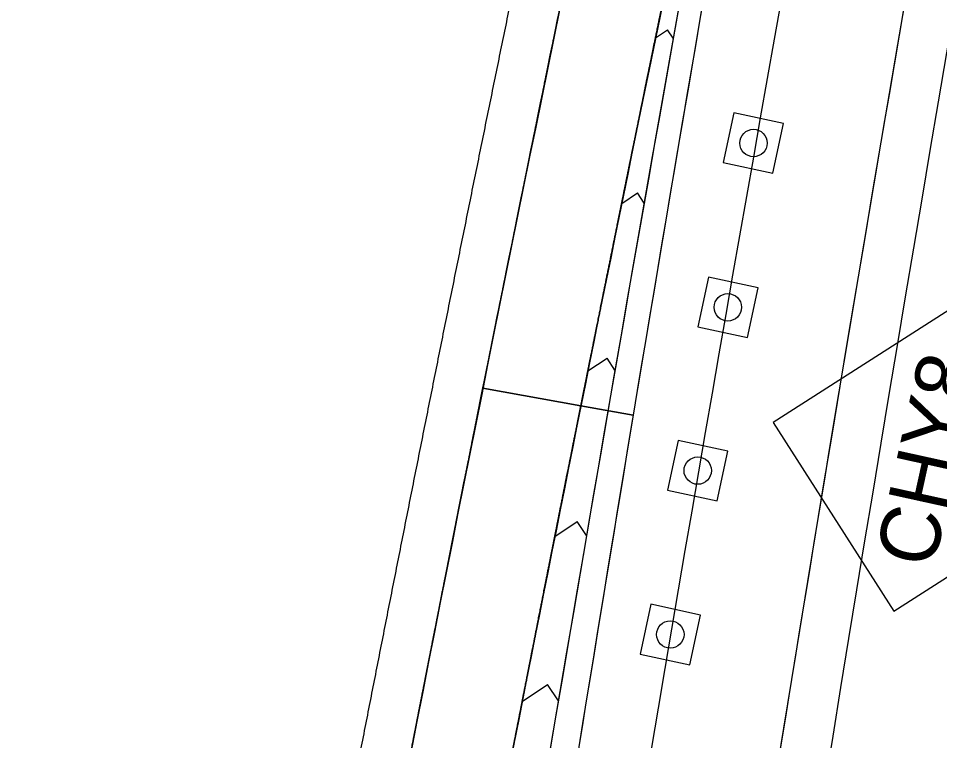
# Model space of a CAD drawing. Extents: x 14104283 to 14121738, y 8635219 to 8671666.
# Drawn here: x 14107950.2 to 14108061.2, y 8640438 to 8640525 of the extents above; entities that cross this region are included whole.
import ezdxf

# ---------------------------------------------------------------- set-up
doc = ezdxf.new("R2010")
doc.units = 0
for name, color, linetype in [('Cell', 7, 'Continuous'), ('Default', 7, 'Continuous'), ('dsnPaintExistingBrokenLaneLineWhite', 7, 'Continuous'), ('dsnPaintExistingChannelizingLaneWhite', 7, 'Continuous'), ('dsnPaintExistingEdgeLineRightWhite', 7, 'Continuous'), ('dsnStdLabel', 7, 'Continuous'), ('dsnStgShadingPrevPav', 7, 'Continuous')]:
    doc.layers.add(name, color=color, linetype=linetype)

msp = doc.modelspace()

# ---------------------------------------------------------------- linework, layer by layer
at = {"layer": 'Cell'}
for points in [[(14108041.1, 8640506.32), (14108042.39, 8640512.31), (14108036.4, 8640513.6), (14108035.11, 8640507.61), (14108041.1, 8640506.32)], [(14108041.1, 8640506.32), (14108042.39, 8640512.31), (14108036.4, 8640513.6), (14108035.11, 8640507.61), (14108041.1, 8640506.32)], [(14108038.02, 8640486.52), (14108039.31, 8640492.51), (14108033.32, 8640493.8), (14108032.03, 8640487.81), (14108038.02, 8640486.52)], [(14108038.02, 8640486.52), (14108039.31, 8640492.51), (14108033.32, 8640493.8), (14108032.03, 8640487.81), (14108038.02, 8640486.52)], [(14108034.38, 8640466.84), (14108035.67, 8640472.83), (14108029.68, 8640474.12), (14108028.39, 8640468.13), (14108034.38, 8640466.84)], [(14108034.38, 8640466.84), (14108035.67, 8640472.83), (14108029.68, 8640474.12), (14108028.39, 8640468.13), (14108034.38, 8640466.84)], [(14108031.08, 8640447.09), (14108032.37, 8640453.08), (14108026.38, 8640454.37), (14108025.09, 8640448.38), (14108031.08, 8640447.09)], [(14108031.08, 8640447.09), (14108032.37, 8640453.08), (14108026.38, 8640454.37), (14108025.09, 8640448.38), (14108031.08, 8640447.09)]]:
    msp.add_lwpolyline(points, dxfattribs=at)
for centre in [(14108038.75, 8640509.96), (14108038.75, 8640509.96), (14108035.67, 8640490.16), (14108035.67, 8640490.16), (14108032.03, 8640470.48), (14108032.03, 8640470.48), (14108028.73, 8640450.73), (14108028.73, 8640450.73)]:
    msp.add_circle(centre, 1.65, dxfattribs=at)
at = {"layer": 'Default'}
for centre, radius, start, end in [((14117394.14, 8638857.08), 9512, 167.610212, 171.325989), ((14117394.14, 8638857.08), 9500, 167.610212, 171.325989), ((14117342.69, 8638609.63), 9522.13, 167.509575, 168.915877), ((14117342.69, 8638609.63), 9510.13, 167.921867, 168.915877), ((14117350.61, 8638608.07), 9530.2, 168.915826, 170.320937)]:
    msp.add_arc(centre, radius, start, end, dxfattribs=at)
at = {"layer": 'dsnPaintExistingBrokenLaneLineWhite'}
msp.add_arc((14117394.14, 8638857.08), 9500, 167.610212, 171.325989, dxfattribs=at)
at = {"layer": 'dsnPaintExistingChannelizingLaneWhite'}
for p, q in [((14108026.95, 8640522.65), (14108028.41, 8640523.61)), ((14108029.08, 8640522.59), (14108028.41, 8640523.61)), ((14108022.87, 8640502.69), (14108024.77, 8640503.94)), ((14108025.58, 8640502.72), (14108024.77, 8640503.94)), ((14108018.8, 8640482.51), (14108021.1, 8640484.04)), ((14108022.06, 8640482.58), (14108021.1, 8640484.04)), ((14108014.81, 8640462.56), (14108017.51, 8640464.36)), ((14108018.63, 8640462.68), (14108017.51, 8640464.36)), ((14108010.88, 8640442.64), (14108013.92, 8640444.69)), ((14108015.24, 8640442.73), (14108013.92, 8640444.69))]:
    msp.add_line(p, q, dxfattribs=at)
for centre, radius, start, end in [((14117394.14, 8638857.08), 9512, 169.444425, 171.325989), ((14117342.69, 8638609.63), 9510.13, 167.921867, 168.915877)]:
    msp.add_arc(centre, radius, start, end, dxfattribs=at)
at = {"layer": 'dsnPaintExistingEdgeLineRightWhite'}
for centre, radius, start, end in [((14117342.69, 8638609.63), 9522.13, 167.509575, 168.915877), ((14117350.61, 8638608.07), 9530.2, 168.915826, 170.320937)]:
    msp.add_arc(centre, radius, start, end, dxfattribs=at)
at = {"layer": 'dsnStdLabel'}
msp.add_lwpolyline([(14108055.67, 8640453.53), (14108078.42, 8640468.08), (14108063.87, 8640490.82), (14108041.12, 8640476.27)], close=True, dxfattribs=at)
at = {"layer": 'dsnStgShadingPrevPav'}
for p, q in [((14108006.14, 8640480.41), (14108017.94, 8640478.29)), ((14108017.94, 8640478.29), (14108006.14, 8640480.41)), ((14108017.94, 8640478.29), (14108024.25, 8640477.15)), ((14108024.25, 8640477.15), (14108017.94, 8640478.29))]:
    msp.add_line(p, q, dxfattribs=at)
for radius, start, end in [(9488, 167.610212, 172.222077), (9482, 167.610212, 172.222077), (9512, 169.413861, 172.222077), (9512, 169.413861, 170.574102), (9488, 169.413861, 172.222077), (9512, 170.574102, 171.702544)]:
    msp.add_arc((14117407.82, 8638919.35), radius, start, end, dxfattribs=at)
for points, degree in [([(14108040.07, 8640670.33), (14108039.11, 8640666.01), (14108035.79, 8640651.03), (14108029.85, 8640623.7), (14108025.19, 8640602.04), (14108020.26, 8640578.84), (14108015.47, 8640556.04), (14108010.72, 8640533.12), (14108006.03, 8640510.22), (14108001.39, 8640487.29), (14107996.81, 8640464.36), (14107992.28, 8640441.41), (14107987.82, 8640418.46), (14107983.4, 8640395.49), (14107979.05, 8640372.51), (14107974.75, 8640349.53), (14107970.51, 8640326.51), (14107966.33, 8640303.59), (14107962.15, 8640280.24), (14107958.29, 8640258.43), (14107953.48, 8640230.88), (14107950.9, 8640215.75), (14107950.15, 8640211.39)], 2), ([(14107956.07, 8640210.37), (14107957.38, 8640218.06), (14107960.02, 8640233.43), (14107964.04, 8640256.47), (14107968.11, 8640279.5), (14107972.24, 8640302.51), (14107976.42, 8640325.52), (14107980.66, 8640348.51), (14107984.96, 8640371.49), (14107989.32, 8640394.46), (14107993.73, 8640417.41), (14107998.19, 8640440.35), (14108002.71, 8640463.28), (14108007.29, 8640486.2), (14108011.92, 8640509.1), (14108016.61, 8640531.99), (14108021.36, 8640554.87), (14108026.16, 8640577.73), (14108031.01, 8640600.58), (14108035.93, 8640623.41), (14108040.89, 8640646.24), (14108044.25, 8640661.44), (14108045.92, 8640669.04)], 3), ([(14108014.97, 8640523.98), (14108015.44, 8640526.27), (14108015.91, 8640528.56), (14108016.39, 8640530.85)], 2), ([(14108028.21, 8640528.82), (14108027.82, 8640526.91), (14108027.43, 8640525.01), (14108027.04, 8640523.1)], 2), ([(14108027.04, 8640523.1), (14108027.43, 8640525.01), (14108027.82, 8640526.91), (14108028.21, 8640528.82)], 2), ([(14108014.74, 8640522.84), (14108014.82, 8640523.22), (14108014.9, 8640523.6), (14108014.97, 8640523.98)], 2), ([(14108013.33, 8640515.97), (14108013.8, 8640518.26), (14108014.27, 8640520.55), (14108014.74, 8640522.84)], 2), ([(14108027.04, 8640523.1), (14108026.72, 8640521.58), (14108026.41, 8640520.05), (14108026.1, 8640518.53)], 2), ([(14108026.1, 8640518.53), (14108026.41, 8640520.05), (14108026.72, 8640521.58), (14108027.04, 8640523.1)], 2), ([(14108026.1, 8640518.53), (14108026.02, 8640518.15), (14108025.94, 8640517.77), (14108025.86, 8640517.39)], 2), ([(14108025.86, 8640517.39), (14108025.94, 8640517.77), (14108026.02, 8640518.15), (14108026.1, 8640518.53)], 2), ([(14108025.86, 8640517.39), (14108025.71, 8640516.63), (14108025.55, 8640515.86), (14108025.4, 8640515.1)], 2), ([(14108025.4, 8640515.1), (14108025.55, 8640515.86), (14108025.71, 8640516.63), (14108025.86, 8640517.39)], 2), ([(14108012.4, 8640511.39), (14108012.71, 8640512.92), (14108013.02, 8640514.44), (14108013.33, 8640515.97)], 2), ([(14108025.4, 8640515.1), (14108025.24, 8640514.34), (14108025.09, 8640513.58), (14108024.93, 8640512.81)], 2), ([(14108024.93, 8640512.81), (14108025.09, 8640513.58), (14108025.24, 8640514.34), (14108025.4, 8640515.1)], 2), ([(14108024.93, 8640512.81), (14108024.7, 8640511.67), (14108024.46, 8640510.53), (14108024.23, 8640509.38)], 2), ([(14108024.23, 8640509.38), (14108024.46, 8640510.53), (14108024.7, 8640511.67), (14108024.93, 8640512.81)], 2), ([(14108012.17, 8640510.25), (14108012.24, 8640510.63), (14108012.32, 8640511.01), (14108012.4, 8640511.39)], 2), ([(14108011.93, 8640509.1), (14108012.01, 8640509.48), (14108012.09, 8640509.86), (14108012.17, 8640510.25)], 2), ([(14108024.23, 8640509.38), (14108024.15, 8640509), (14108024.07, 8640508.62), (14108024, 8640508.24)], 2), ([(14108024, 8640508.24), (14108024.07, 8640508.62), (14108024.15, 8640509), (14108024.23, 8640509.38)], 2), ([(14108011.47, 8640506.81), (14108011.62, 8640507.57), (14108011.78, 8640508.34), (14108011.93, 8640509.1)], 2), ([(14108024, 8640508.24), (14108023.92, 8640507.86), (14108023.84, 8640507.48), (14108023.76, 8640507.1)], 2), ([(14108023.76, 8640507.1), (14108023.84, 8640507.48), (14108023.92, 8640507.86), (14108024, 8640508.24)], 2), ([(14108023.76, 8640507.1), (14108023.69, 8640506.72), (14108023.61, 8640506.34), (14108023.53, 8640505.95)], 2), ([(14108023.53, 8640505.95), (14108023.61, 8640506.34), (14108023.69, 8640506.72), (14108023.76, 8640507.1)], 2), ([(14108010.77, 8640503.38), (14108011, 8640504.52), (14108011.23, 8640505.67), (14108011.47, 8640506.81)], 2), ([(14108023.53, 8640505.95), (14108023.45, 8640505.57), (14108023.38, 8640505.19), (14108023.3, 8640504.81)], 2), ([(14108023.3, 8640504.81), (14108023.38, 8640505.19), (14108023.45, 8640505.57), (14108023.53, 8640505.95)], 2), ([(14108023.3, 8640504.81), (14108023.22, 8640504.43), (14108023.14, 8640504.05), (14108023.07, 8640503.67)], 2), ([(14108023.07, 8640503.67), (14108023.14, 8640504.05), (14108023.22, 8640504.43), (14108023.3, 8640504.81)], 2), ([(14108023.07, 8640503.67), (14108022.99, 8640503.29), (14108022.91, 8640502.91), (14108022.83, 8640502.52)], 2), ([(14108022.83, 8640502.52), (14108022.91, 8640502.91), (14108022.99, 8640503.29), (14108023.07, 8640503.67)], 2), ([(14108010.3, 8640501.09), (14108010.46, 8640501.85), (14108010.61, 8640502.61), (14108010.77, 8640503.38)], 2), ([(14108022.83, 8640502.52), (14108022.76, 8640502.14), (14108022.68, 8640501.76), (14108022.6, 8640501.38)], 2), ([(14108022.6, 8640501.38), (14108022.68, 8640501.76), (14108022.76, 8640502.14), (14108022.83, 8640502.52)], 2), ([(14108022.6, 8640501.38), (14108022.52, 8640501), (14108022.45, 8640500.62), (14108022.37, 8640500.24)], 2), ([(14108022.37, 8640500.24), (14108022.45, 8640500.62), (14108022.52, 8640501), (14108022.6, 8640501.38)], 2), ([(14108009.38, 8640496.5), (14108009.69, 8640498.03), (14108009.99, 8640499.56), (14108010.3, 8640501.09)], 2), ([(14108022.37, 8640500.24), (14108021.98, 8640498.33), (14108021.6, 8640496.43), (14108021.21, 8640494.52)], 2), ([(14108021.21, 8640494.52), (14108021.6, 8640496.43), (14108021.98, 8640498.33), (14108022.37, 8640500.24)], 2), ([(14108009.15, 8640495.36), (14108009.22, 8640495.74), (14108009.3, 8640496.12), (14108009.38, 8640496.5)], 2), ([(14108008.45, 8640491.92), (14108008.68, 8640493.07), (14108008.91, 8640494.21), (14108009.15, 8640495.36)], 2), ([(14108021.21, 8640494.52), (14108020.52, 8640491.09), (14108019.83, 8640487.66), (14108019.14, 8640484.22)], 2), ([(14108019.14, 8640484.22), (14108019.83, 8640487.66), (14108020.52, 8640491.09), (14108021.21, 8640494.52)], 2), ([(14108007.99, 8640489.63), (14108008.14, 8640490.4), (14108008.3, 8640491.16), (14108008.45, 8640491.92)], 2), ([(14108007.76, 8640488.49), (14108007.84, 8640488.87), (14108007.91, 8640489.25), (14108007.99, 8640489.63)], 2), ([(14108007.53, 8640487.34), (14108007.61, 8640487.72), (14108007.68, 8640488.11), (14108007.76, 8640488.49)], 2), ([(14108007.3, 8640486.2), (14108007.38, 8640486.58), (14108007.45, 8640486.96), (14108007.53, 8640487.34)], 2), ([(14108006.84, 8640483.91), (14108006.99, 8640484.67), (14108007.15, 8640485.43), (14108007.3, 8640486.2)], 2), ([(14108006.38, 8640481.61), (14108006.53, 8640482.38), (14108006.69, 8640483.14), (14108006.84, 8640483.91)], 2), ([(14108019.14, 8640484.22), (14108019.06, 8640483.84), (14108018.98, 8640483.46), (14108018.91, 8640483.08)], 2), ([(14108018.91, 8640483.08), (14108018.98, 8640483.46), (14108019.06, 8640483.84), (14108019.14, 8640484.22)], 2), ([(14108018.91, 8640483.08), (14108018.75, 8640482.32), (14108018.6, 8640481.55), (14108018.45, 8640480.79)], 2), ([(14108018.45, 8640480.79), (14108018.6, 8640481.55), (14108018.75, 8640482.32), (14108018.91, 8640483.08)], 2), ([(14108006.14, 8640480.41), (14108006.22, 8640480.81), (14108006.3, 8640481.21), (14108006.38, 8640481.61)], 2), ([(14108005.46, 8640477.03), (14108005.69, 8640478.16), (14108005.91, 8640479.28), (14108006.14, 8640480.41)], 2), ([(14108018.45, 8640480.79), (14108018.29, 8640480.03), (14108018.14, 8640479.27), (14108017.99, 8640478.5)], 2), ([(14108017.99, 8640478.5), (14108018.14, 8640479.27), (14108018.29, 8640480.03), (14108018.45, 8640480.79)], 2), ([(14108017.94, 8640478.29), (14108017.88, 8640477.98), (14108017.82, 8640477.67), (14108017.76, 8640477.36)], 2), ([(14108017.76, 8640477.36), (14108017.82, 8640477.67), (14108017.88, 8640477.98), (14108017.94, 8640478.29)], 2), ([(14108017.99, 8640478.5), (14108017.97, 8640478.43), (14108017.96, 8640478.36), (14108017.94, 8640478.29)], 2), ([(14108017.94, 8640478.29), (14108017.96, 8640478.36), (14108017.97, 8640478.43), (14108017.99, 8640478.5)], 2), ([(14108005.23, 8640475.89), (14108005.31, 8640476.27), (14108005.38, 8640476.65), (14108005.46, 8640477.03)], 2), ([(14108017.76, 8640477.36), (14108017.68, 8640476.98), (14108017.61, 8640476.6), (14108017.53, 8640476.22)], 2), ([(14108017.53, 8640476.22), (14108017.61, 8640476.6), (14108017.68, 8640476.98), (14108017.76, 8640477.36)], 2), ([(14108005, 8640474.74), (14108005.08, 8640475.12), (14108005.16, 8640475.5), (14108005.23, 8640475.89)], 2), ([(14108017.53, 8640476.22), (14108016.84, 8640472.78), (14108016.16, 8640469.35), (14108015.47, 8640465.92)], 2), ([(14108015.47, 8640465.92), (14108016.16, 8640469.35), (14108016.84, 8640472.78), (14108017.53, 8640476.22)], 2), ([(14108003.63, 8640467.87), (14108004.09, 8640470.16), (14108004.55, 8640472.45), (14108005, 8640474.74)], 2), ([(14108003.4, 8640466.72), (14108003.48, 8640467.1), (14108003.56, 8640467.48), (14108003.63, 8640467.87)], 2), ([(14108002.72, 8640463.28), (14108002.95, 8640464.43), (14108003.18, 8640465.57), (14108003.4, 8640466.72)], 2), ([(14108015.47, 8640465.92), (14108015.4, 8640465.53), (14108015.32, 8640465.15), (14108015.25, 8640464.77)], 2), ([(14108015.25, 8640464.77), (14108015.32, 8640465.15), (14108015.4, 8640465.53), (14108015.47, 8640465.92)], 2), ([(14108015.25, 8640464.77), (14108015.17, 8640464.39), (14108015.09, 8640464.01), (14108015.02, 8640463.63)], 2), ([(14108015.02, 8640463.63), (14108015.09, 8640464.01), (14108015.17, 8640464.39), (14108015.25, 8640464.77)], 2), ([(14108015.02, 8640463.63), (14108014.87, 8640462.86), (14108014.71, 8640462.1), (14108014.56, 8640461.34)], 2), ([(14108014.56, 8640461.34), (14108014.71, 8640462.1), (14108014.87, 8640462.86), (14108015.02, 8640463.63)], 2), ([(14108002.49, 8640462.13), (14108002.57, 8640462.52), (14108002.65, 8640462.9), (14108002.72, 8640463.28)], 2), ([(14108002.27, 8640460.99), (14108002.34, 8640461.37), (14108002.42, 8640461.75), (14108002.49, 8640462.13)], 2), ([(14108002.04, 8640459.84), (14108002.12, 8640460.22), (14108002.19, 8640460.61), (14108002.27, 8640460.99)], 2), ([(14108014.56, 8640461.34), (14108014.41, 8640460.57), (14108014.26, 8640459.81), (14108014.11, 8640459.05)], 2), ([(14108014.11, 8640459.05), (14108014.26, 8640459.81), (14108014.41, 8640460.57), (14108014.56, 8640461.34)], 2), ([(14108001.13, 8640455.26), (14108001.43, 8640456.79), (14108001.74, 8640458.31), (14108002.04, 8640459.84)], 2), ([(14108014.11, 8640459.05), (14108013.5, 8640455.99), (14108012.9, 8640452.94), (14108012.3, 8640449.89)], 2), ([(14108012.3, 8640449.89), (14108012.9, 8640452.94), (14108013.5, 8640455.99), (14108014.11, 8640459.05)], 2), ([(14108000.91, 8640454.11), (14108000.98, 8640454.49), (14108001.06, 8640454.87), (14108001.13, 8640455.26)], 2), ([(14107999.78, 8640448.38), (14108000.15, 8640450.29), (14108000.53, 8640452.2), (14108000.91, 8640454.11)], 2), ([(14108012.3, 8640449.89), (14108011.92, 8640447.98), (14108011.55, 8640446.07), (14108011.17, 8640444.16)], 2), ([(14108011.17, 8640444.16), (14108011.55, 8640446.07), (14108011.92, 8640447.98), (14108012.3, 8640449.89)], 2), ([(14107999.55, 8640447.23), (14107999.63, 8640447.61), (14107999.7, 8640448), (14107999.78, 8640448.38)], 2), ([(14107998.87, 8640443.79), (14107999.1, 8640444.94), (14107999.33, 8640446.09), (14107999.55, 8640447.23)], 2), ([(14107998.2, 8640440.35), (14107998.42, 8640441.5), (14107998.65, 8640442.65), (14107998.87, 8640443.79)], 2), ([(14108011.17, 8640444.16), (14108010.87, 8640442.64), (14108010.57, 8640441.11), (14108010.27, 8640439.58)], 2), ([(14108010.27, 8640439.58), (14108010.57, 8640441.11), (14108010.87, 8640442.64), (14108011.17, 8640444.16)], 2), ([(14107997.98, 8640439.2), (14107998.05, 8640439.59), (14107998.13, 8640439.97), (14107998.2, 8640440.35)], 2), ([(14107997.75, 8640438.06), (14107997.83, 8640438.44), (14107997.9, 8640438.82), (14107997.98, 8640439.2)], 2), ([(14108010.27, 8640439.58), (14108010.2, 8640439.2), (14108010.12, 8640438.82), (14108010.05, 8640438.44)], 2), ([(14108010.05, 8640438.44), (14108010.12, 8640438.82), (14108010.2, 8640439.2), (14108010.27, 8640439.58)], 2), ([(14108010.05, 8640438.44), (14108009.9, 8640437.67), (14108009.75, 8640436.91), (14108009.6, 8640436.15)], 2), ([(14108009.6, 8640436.15), (14108009.75, 8640436.91), (14108009.9, 8640437.67), (14108010.05, 8640438.44)], 2), ([(14107995.51, 8640426.59), (14107996.26, 8640430.41), (14107997, 8640434.24), (14107997.75, 8640438.06)], 2)]:
    msp.add_open_spline(points, degree=degree, dxfattribs=at)

# ---------------------------------------------------------------- texts
at = {"layer": 'dsnStdLabel'}
msp.add_text('CHY8', height=7.2, rotation=77.6078, dxfattribs=at).set_placement((14108060.45, 8640458.52))

doc.saveas('drawing.dxf')
